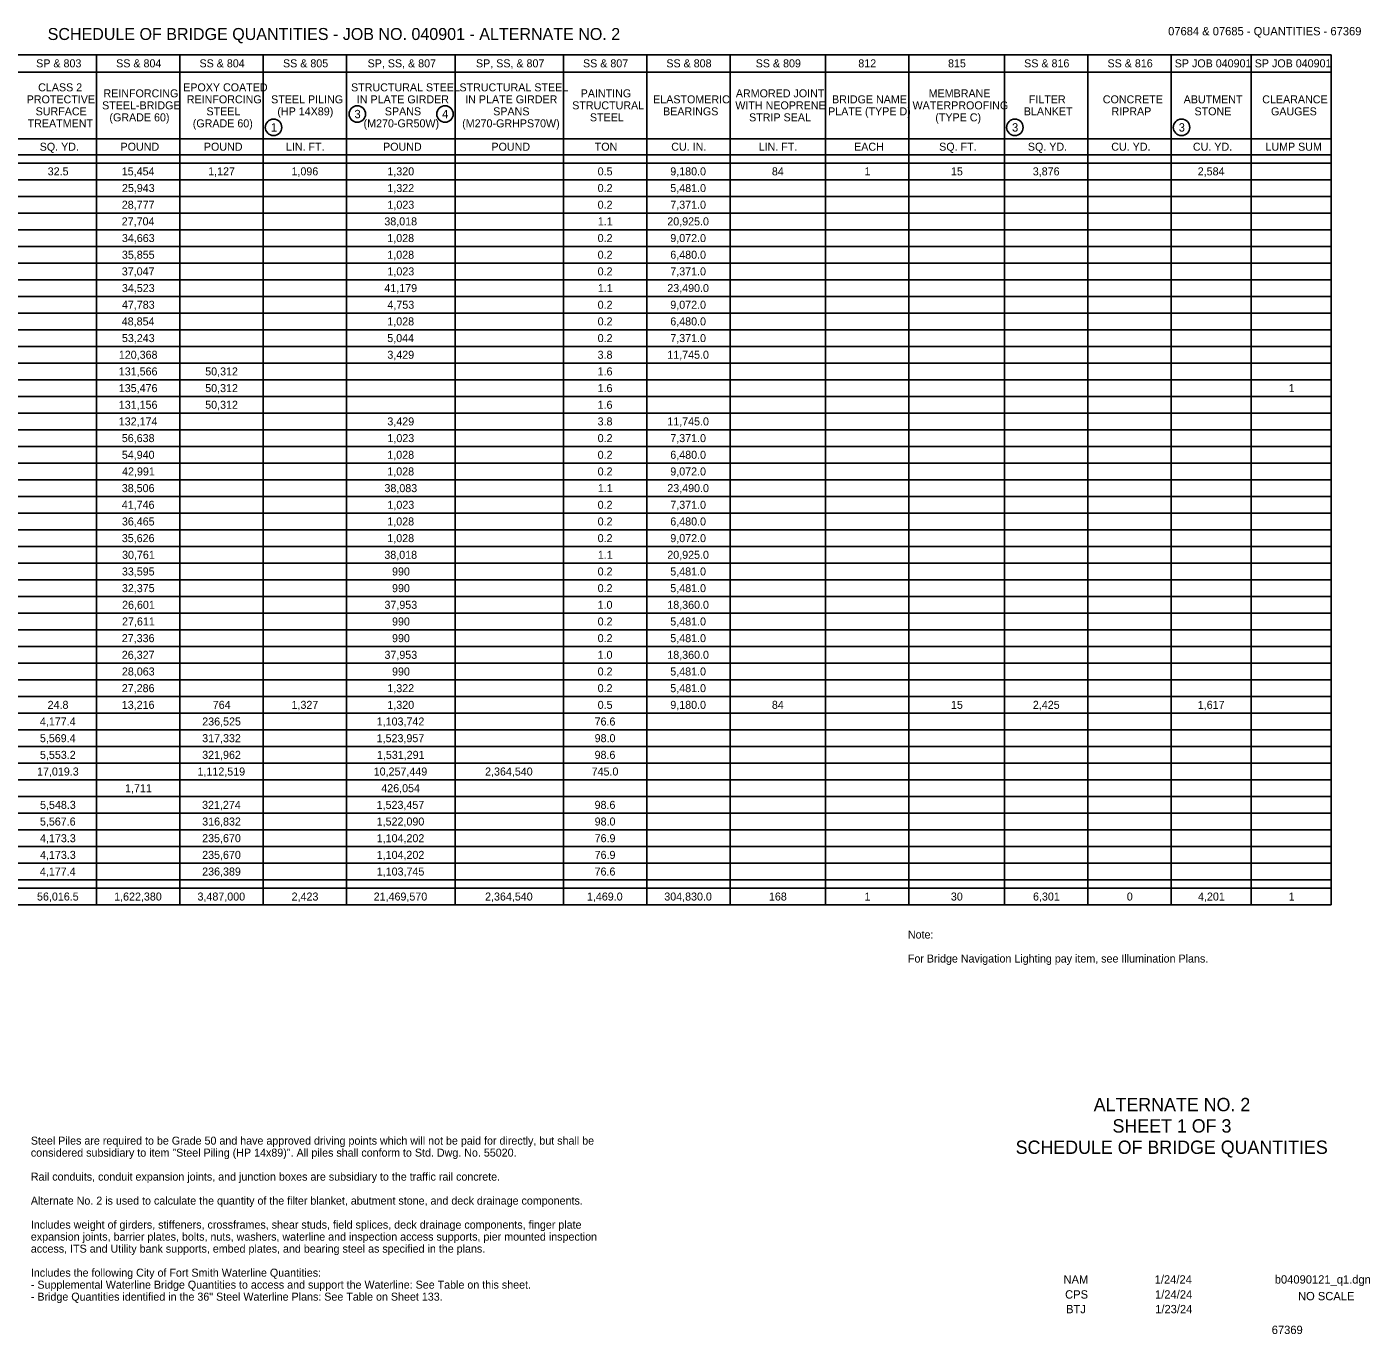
# Model space of a CAD drawing. Extents: x 0.06 to 1.36, y 0.04 to 0.85.
# Drawn here: x 0.519 to 1.358, y 0.037 to 0.854 of the extents above; entities that cross this region are included whole.
import ezdxf

# ---------------------------------------------------------------- set-up
doc = ezdxf.new("R2010")
doc.units = 0
for name, color, linetype in [('R_ROW', 7, 'Continuous'), ('R_Shade By Others', 7, 'Continuous'), ('R_Survey Control', 7, 'Continuous'), ('R_Wall', 7, 'Continuous')]:
    doc.layers.add(name, color=color, linetype=linetype)

msp = doc.modelspace()

# ---------------------------------------------------------------- linework, layer by layer
at = {"layer": 'R_Survey Control'}
for p, q in [((0.07508, 0.83695), (1.33392, 0.83695)), ((0.56236, 0.83695), (0.56236, 0.3057)), ((0.61444, 0.83695), (0.61444, 0.3057)), ((0.66653, 0.83695), (0.66653, 0.3057)), ((0.71861, 0.83695), (0.71861, 0.3057)), ((0.78632, 0.83695), (0.78632, 0.3057)), ((0.85407, 0.83695), (0.85407, 0.3057)), ((0.90615, 0.83695), (0.90615, 0.3057)), ((0.95823, 0.83695), (0.95823, 0.3057)), ((1.0178, 0.83695), (1.0178, 0.3057)), ((1.06988, 0.83695), (1.06988, 0.3057)), ((1.12978, 0.83695), (1.12978, 0.3057)), ((1.18186, 0.83695), (1.18186, 0.3057)), ((1.23394, 0.83695), (1.23394, 0.3057)), ((1.28392, 0.83695), (1.28392, 0.3057)), ((1.33392, 0.83695), (1.33392, 0.3057)), ((0.2593, 0.78445), (1.33392, 0.78445)), ((0.07508, 0.77445), (1.33392, 0.77445)), ((0.11154, 0.76924), (1.33392, 0.76924)), ((0.11154, 0.75883), (1.33392, 0.75883)), ((0.11154, 0.74841), (1.33392, 0.74841)), ((0.11154, 0.73799), (1.33392, 0.73799)), ((0.11154, 0.72758), (1.33392, 0.72758)), ((0.11154, 0.71716), (1.33392, 0.71716)), ((0.11154, 0.70674), (1.33392, 0.70674)), ((0.11154, 0.69633), (1.33392, 0.69633)), ((0.11154, 0.68591), (1.33392, 0.68591)), ((0.11154, 0.67549), (1.33392, 0.67549)), ((0.11154, 0.66508), (1.33392, 0.66508)), ((0.11154, 0.65466), (1.33392, 0.65466)), ((0.11154, 0.64424), (1.33392, 0.64424)), ((0.11154, 0.63383), (1.33392, 0.63383)), ((0.11154, 0.62341), (1.33392, 0.62341)), ((0.11154, 0.61299), (1.33392, 0.61299)), ((0.11154, 0.60258), (1.33392, 0.60258)), ((0.11154, 0.59216), (1.33392, 0.59216)), ((0.11154, 0.58174), (1.33392, 0.58174)), ((0.11154, 0.57133), (1.33392, 0.57133)), ((0.11154, 0.56091), (1.33392, 0.56091)), ((0.11154, 0.55049), (1.33392, 0.55049)), ((0.11154, 0.54008), (1.33392, 0.54008)), ((0.11154, 0.52966), (1.33392, 0.52966)), ((0.11154, 0.51924), (1.33392, 0.51924)), ((0.11154, 0.50883), (1.33392, 0.50883)), ((0.11154, 0.49841), (1.33392, 0.49841)), ((0.11154, 0.48799), (1.33392, 0.48799)), ((0.11154, 0.47758), (1.33392, 0.47758)), ((0.11154, 0.46716), (1.33392, 0.46716)), ((0.11154, 0.45674), (1.33392, 0.45674)), ((0.11154, 0.44633), (1.33392, 0.44633)), ((0.11154, 0.43591), (1.33392, 0.43591)), ((0.11154, 0.42549), (1.33392, 0.42549)), ((0.11154, 0.41508), (1.33392, 0.41508)), ((0.11154, 0.40466), (1.33392, 0.40466)), ((0.11154, 0.39424), (1.33392, 0.39424)), ((0.11154, 0.38383), (1.33392, 0.38383)), ((0.11154, 0.37341), (1.33392, 0.37341)), ((0.11154, 0.36299), (1.33392, 0.36299)), ((0.11154, 0.35258), (1.33392, 0.35258)), ((0.11154, 0.34216), (1.33392, 0.34216)), ((0.11154, 0.33174), (1.33392, 0.33174)), ((0.11154, 0.32133), (1.33392, 0.32133)), ((0.07508, 0.31612), (1.33392, 0.31612)), ((0.07508, 0.3057), (1.33392, 0.3057))]:
    msp.add_line(p, q, dxfattribs=at)
msp.add_lwpolyline([(0.2593, 0.82612), (0.30758, 0.82612), (0.41883, 0.82612), (0.46733, 0.82612), (0.509, 0.82612), (0.55587, 0.82612), (0.58452, 0.82612), (0.6366, 0.82612), (0.68087, 0.82612), (0.74858, 0.82612), (0.79433, 0.82612), (0.84642, 0.82612), (0.94537, 0.82612), (1.00267, 0.82612), (1.06517, 0.82612), (1.19277, 0.82612), (1.26048, 0.82612), (1.31256, 0.82612), (1.33392, 0.82612)], dxfattribs=at)
at = {"layer": 'R_Wall'}
for centre in [(0.72525, 0.79986), (0.78009, 0.79986), (0.67293, 0.79152), (1.13618, 0.79152), (1.24035, 0.79152)]:
    msp.add_circle(centre, 0.00515, dxfattribs=at)

# ---------------------------------------------------------------- texts
at = {"layer": 'R_ROW'}
msp.add_text('SCHEDULE OF BRIDGE QUANTITIES - JOB NO. 040901 - ALTERNATE NO. 2', height=0.0075, dxfattribs=at).set_placement((0.53175, 0.84612))
at = {"layer": 'R_Shade By Others'}
for s, height, p in [('07684 & 07685 - QUANTITIES - 67369', 0.0052083, (1.23197, 0.84904)), ('ALTERNATE NO. 2', 0.0083332, (1.18545, 0.17677)), ('SHEET 1 OF 3', 0.0083332, (1.1972, 0.16344)), ('SCHEDULE OF BRIDGE QUANTITIES', 0.0083332, (1.13669, 0.1501)), ('NAM', 0.005208, (1.1666, 0.06906)), ('1/24/24', 0.005208, (1.22357, 0.06906)), ('b04090121_q1.dgn', 0.0052083, (1.29862, 0.06906)), ('CPS', 0.005208, (1.1676, 0.05969)), ('1/24/24', 0.005208, (1.22378, 0.05969)), ('NO SCALE', 0.005208, (1.31316, 0.05864)), ('BTJ', 0.005208, (1.16819, 0.05052)), ('1/23/24', 0.005208, (1.22389, 0.05052)), ('67369', 0.005208, (1.29672, 0.03756))]:
    msp.add_text(s, height=height, dxfattribs=at).set_placement(p)
at = {"layer": 'R_Survey Control'}
for s, p in [('SP & 803', (0.52458, 0.82904)), ('SS & 804', (0.57457, 0.82904)), ('SS & 804', (0.62665, 0.82904)), ('SS & 805', (0.67883, 0.82904)), ('SP, SS, & 807', (0.7317, 0.82904)), ('SP, SS, & 807', (0.79943, 0.82904)), ('SS & 807', (0.86631, 0.82904)), ('SS & 808', (0.91839, 0.82904)), ('SS & 809', (0.97424, 0.82904)), ('812', (1.03836, 0.82904)), ('815', (1.09443, 0.82904)), ('SS & 816', (1.14201, 0.82904)), ('SS & 816', (1.19409, 0.82904)), ('SP JOB 040901', (1.2361, 0.82904)), ('SP JOB 040901', (1.2861, 0.82904)), ('CLASS 2', (0.52582, 0.81404)), ('REINFORCING', (0.56663, 0.81029)), ('EPOXY COATED', (0.61645, 0.81404)), ('STRUCTURAL STEEL', (0.72137, 0.81404)), ('STRUCTURAL STEEL', (0.78909, 0.81404)), ('PAINTING', (0.86485, 0.81029)), ('ARMORED JOINT', (0.96182, 0.81029)), ('MEMBRANE', (1.08232, 0.81029)), ('PROTECTIVE', (0.51866, 0.80654)), ('STEEL-BRIDGE', (0.56578, 0.80279)), ('REINFORCING', (0.61871, 0.80654)), ('STEEL PILING', (0.67141, 0.80654)), ('IN PLATE GIRDER', (0.72497, 0.80654)), ('IN PLATE GIRDER', (0.7927, 0.80654)), ('STRUCTURAL', (0.85957, 0.80279)), ('ELASTOMERIC', (0.91013, 0.80654)), ('WITH NEOPRENE', (0.9615, 0.80279)), ('BRIDGE NAME', (1.02194, 0.80654)), ('WATERPROOFING', (1.07225, 0.80279)), ('FILTER', (1.14491, 0.80654)), ('CONCRETE', (1.19116, 0.80654)), ('ABUTMENT', (1.24169, 0.80654)), ('CLEARANCE', (1.29079, 0.80654)), ('SURFACE', (0.52424, 0.79904)), ('(GRADE 60)', (0.57037, 0.79529)), ('STEEL', (0.631, 0.79904)), ('(HP 14X89)', (0.67532, 0.79904)), ('SPANS', (0.74247, 0.79904)), ('SPANS', (0.81019, 0.79904)), ('STEEL', (0.87063, 0.79529)), ('BEARINGS', (0.91634, 0.79904)), ('STRIP SEAL', (0.9701, 0.79529)), ('PLATE (TYPE D)', (1.01949, 0.79904)), ('(TYPE C)', (1.08648, 0.79529)), ('BLANKET', (1.14177, 0.79904)), ('RIPRAP', (1.19656, 0.79904)), ('STONE', (1.24846, 0.79904)), ('GAUGES', (1.29626, 0.79904)), ('TREATMENT', (0.51926, 0.79154)), ('(GRADE 60)', (0.62245, 0.79154)), ('(M270-GR50W)', (0.7292, 0.79154)), ('(M270-GRHPS70W)', (0.7908, 0.79154)), ('SQ. YD.', (0.52679, 0.77695)), ('POUND', (0.5773, 0.77695)), ('POUND', (0.62938, 0.77695)), ('LIN. FT.', (0.68065, 0.77695)), ('POUND', (0.74136, 0.77695)), ('POUND', (0.80909, 0.77695)), ('TON', (0.87363, 0.77695)), ('CU. IN.', (0.92146, 0.77695)), ('LIN. FT.', (0.97609, 0.77695)), ('EACH', (1.03572, 0.77695)), ('SQ. FT.', (1.0889, 0.77695)), ('SQ. YD.', (1.14432, 0.77695)), ('CU. YD.', (1.19643, 0.77695)), ('CU. YD.', (1.24746, 0.77695)), ('LUMP SUM', (1.29277, 0.77695)), ('32.5', (0.53179, 0.76154)), ('15,454', (0.57806, 0.76154)), ('1,127', (0.63206, 0.76154)), ('1,096', (0.68414, 0.76154)), ('1,320', (0.74406, 0.76154)), ('0.5', (0.87549, 0.76154)), ('9,180.0', (0.92087, 0.76154)), ('84', (0.98435, 0.76154)), ('1', (1.04224, 0.76154)), ('15', (1.09625, 0.76154)), ('3,876', (1.14739, 0.76154)), ('2,584', (1.25047, 0.76154)), ('25,943', (0.57817, 0.75112)), ('1,322', (0.74407, 0.75112)), ('0.2', (0.87547, 0.75112)), ('5,481.0', (0.92087, 0.75112)), ('28,777', (0.5781, 0.7407)), ('1,023', (0.74411, 0.7407)), ('0.2', (0.87547, 0.7407)), ('7,371.0', (0.92087, 0.7407)), ('27,704', (0.57806, 0.73029)), ('38,018', (0.74217, 0.73029)), ('1.1', (0.87559, 0.73029)), ('20,925.0', (0.91899, 0.73029)), ('34,663', (0.57817, 0.71987)), ('1,028', (0.74404, 0.71987)), ('0.2', (0.87547, 0.71987)), ('9,072.0', (0.92087, 0.71987)), ('35,855', (0.57816, 0.70945)), ('1,028', (0.74404, 0.70945)), ('0.2', (0.87547, 0.70945)), ('6,480.0', (0.92087, 0.70945)), ('37,047', (0.5781, 0.69904)), ('1,023', (0.74411, 0.69904)), ('0.2', (0.87547, 0.69904)), ('7,371.0', (0.92087, 0.69904)), ('34,523', (0.57817, 0.68862)), ('41,179', (0.74218, 0.68862)), ('1.1', (0.87559, 0.68862)), ('23,490.0', (0.91899, 0.68862)), ('47,783', (0.57817, 0.6782)), ('4,753', (0.74411, 0.6782)), ('0.2', (0.87547, 0.6782)), ('9,072.0', (0.92087, 0.6782)), ('48,854', (0.57806, 0.66779)), ('1,028', (0.74404, 0.66779)), ('0.2', (0.87547, 0.66779)), ('6,480.0', (0.92087, 0.66779)), ('53,243', (0.57817, 0.65737)), ('5,044', (0.744, 0.65737)), ('0.2', (0.87547, 0.65737)), ('7,371.0', (0.92087, 0.65737)), ('120,368', (0.57623, 0.64695)), ('3,429', (0.74406, 0.64695)), ('3.8', (0.87544, 0.64695)), ('11,745.0', (0.91899, 0.64695)), ('131,566', (0.57622, 0.63654)), ('50,312', (0.63021, 0.63654)), ('1.6', (0.87543, 0.63654)), ('135,476', (0.57622, 0.62612)), ('50,312', (0.63021, 0.62612)), ('1.6', (0.87543, 0.62612)), ('1', (1.30732, 0.62612)), ('131,156', (0.57622, 0.6157)), ('50,312', (0.63021, 0.6157)), ('1.6', (0.87543, 0.6157)), ('132,174', (0.57619, 0.60529)), ('3,429', (0.74406, 0.60529)), ('3.8', (0.87544, 0.60529)), ('11,745.0', (0.91899, 0.60529)), ('56,638', (0.5781, 0.59487)), ('1,023', (0.74411, 0.59487)), ('0.2', (0.87547, 0.59487)), ('7,371.0', (0.92087, 0.59487)), ('54,940', (0.57812, 0.58445)), ('1,028', (0.74404, 0.58445)), ('0.2', (0.87547, 0.58445)), ('6,480.0', (0.92087, 0.58445)), ('42,991', (0.57826, 0.57404)), ('1,028', (0.74404, 0.57404)), ('0.2', (0.87547, 0.57404)), ('9,072.0', (0.92087, 0.57404)), ('38,506', (0.57809, 0.56362)), ('38,083', (0.74224, 0.56362)), ('1.1', (0.87559, 0.56362)), ('23,490.0', (0.91899, 0.56362)), ('41,746', (0.57809, 0.5532)), ('1,023', (0.74411, 0.5532)), ('0.2', (0.87547, 0.5532)), ('7,371.0', (0.92087, 0.5532)), ('36,465', (0.57816, 0.54279)), ('1,028', (0.74404, 0.54279)), ('0.2', (0.87547, 0.54279)), ('6,480.0', (0.92087, 0.54279)), ('35,626', (0.57809, 0.53237)), ('1,028', (0.74404, 0.53237)), ('0.2', (0.87547, 0.53237)), ('9,072.0', (0.92087, 0.53237)), ('30,761', (0.57826, 0.52195)), ('38,018', (0.74217, 0.52195)), ('1.1', (0.87559, 0.52195)), ('20,925.0', (0.91899, 0.52195)), ('33,595', (0.57816, 0.51154)), ('990', (0.74697, 0.51154)), ('0.2', (0.87547, 0.51154)), ('5,481.0', (0.92087, 0.51154)), ('32,375', (0.57816, 0.50112)), ('990', (0.74697, 0.50112)), ('0.2', (0.87547, 0.50112)), ('5,481.0', (0.92087, 0.50112)), ('26,601', (0.57826, 0.4907)), ('37,953', (0.74224, 0.4907)), ('1.0', (0.87545, 0.4907)), ('18,360.0', (0.91899, 0.4907)), ('27,611', (0.57826, 0.48029)), ('990', (0.74697, 0.48029)), ('0.2', (0.87547, 0.48029)), ('5,481.0', (0.92087, 0.48029)), ('27,336', (0.57809, 0.46987)), ('990', (0.74697, 0.46987)), ('0.2', (0.87547, 0.46987)), ('5,481.0', (0.92087, 0.46987)), ('26,327', (0.5781, 0.45945)), ('37,953', (0.74224, 0.45945)), ('1.0', (0.87545, 0.45945)), ('18,360.0', (0.91899, 0.45945)), ('28,063', (0.57817, 0.44904)), ('990', (0.74697, 0.44904)), ('0.2', (0.87547, 0.44904)), ('5,481.0', (0.92087, 0.44904)), ('27,286', (0.57809, 0.43862)), ('1,322', (0.74407, 0.43862)), ('0.2', (0.87547, 0.43862)), ('5,481.0', (0.92087, 0.43862)), ('24.8', (0.53174, 0.4282)), ('13,216', (0.57809, 0.4282)), ('764', (0.63494, 0.4282)), ('1,327', (0.68415, 0.4282)), ('1,320', (0.74406, 0.4282)), ('0.5', (0.87549, 0.4282)), ('9,180.0', (0.92087, 0.4282)), ('84', (0.98435, 0.4282)), ('15', (1.09625, 0.4282)), ('2,425', (1.14745, 0.4282)), ('1,617', (1.25051, 0.4282)), ('4,177.4', (0.52691, 0.41779)), ('236,525', (0.62837, 0.41779)), ('1,103,742', (0.7374, 0.41779)), ('76.6', (0.87355, 0.41779)), ('5,569.4', (0.52691, 0.40737)), ('317,332', (0.62834, 0.40737)), ('1,523,957', (0.73737, 0.40737)), ('98.0', (0.87358, 0.40737)), ('5,553.2', (0.52697, 0.39695)), ('321,962', (0.62834, 0.39695)), ('1,531,291', (0.73753, 0.39695)), ('98.6', (0.87355, 0.39695)), ('17,019.3', (0.52514, 0.38654)), ('1,112,519', (0.62541, 0.38654)), ('10,257,449', (0.73551, 0.38654)), ('2,364,540', (0.80512, 0.38654)), ('745.0', (0.8717, 0.38654)), ('1,711', (0.58013, 0.37612)), ('426,054', (0.74025, 0.37612)), ('5,548.3', (0.52702, 0.3657)), ('321,274', (0.62827, 0.3657)), ('1,523,457', (0.73737, 0.3657)), ('98.6', (0.87355, 0.3657)), ('5,567.6', (0.52693, 0.35529)), ('316,832', (0.62834, 0.35529)), ('1,522,090', (0.73739, 0.35529)), ('98.0', (0.87358, 0.35529)), ('4,173.3', (0.52702, 0.34487)), ('235,670', (0.62832, 0.34487)), ('1,104,202', (0.7374, 0.34487)), ('76.9', (0.87358, 0.34487)), ('4,173.3', (0.52702, 0.33445)), ('235,670', (0.62832, 0.33445)), ('1,104,202', (0.7374, 0.33445)), ('76.9', (0.87358, 0.33445)), ('4,177.4', (0.52691, 0.32404)), ('236,389', (0.62833, 0.32404)), ('1,103,745', (0.73743, 0.32404)), ('76.6', (0.87355, 0.32404)), ('56,016.5', (0.52512, 0.30841)), ('1,622,380', (0.57332, 0.30841)), ('3,487,000', (0.62541, 0.30841)), ('2,423', (0.68422, 0.30841)), ('21,469,570', (0.73551, 0.30841)), ('2,364,540', (0.80512, 0.30841)), ('1,469.0', (0.86878, 0.30841)), ('304,830.0', (0.91711, 0.30841)), ('168', (0.98251, 0.30841)), ('1', (1.04224, 0.30841)), ('30', (1.09621, 0.30841)), ('6,301', (1.14755, 0.30841)), ('0', (1.20616, 0.30841)), ('4,201', (1.25066, 0.30841)), ('1', (1.30732, 0.30841)), ('Note:', (1.06935, 0.28467)), ('For Bridge Navigation Lighting pay item, see Illumination Plans.', (1.06935, 0.26967))]:
    msp.add_text(s, height=0.005, dxfattribs=at).set_placement(p)
at = {"layer": 'R_Wall'}
for s, height, p in [('3', 0.00521, (0.7235, 0.79725)), ('4', 0.00521, (0.77822, 0.79725)), ('1', 0.00521, (0.67127, 0.78892)), ('3', 0.00521, (1.13443, 0.78892)), ('3', 0.00521, (1.2386, 0.78892)), ('Steel Piles are required to be Grade 50 and have approved driving points which will not be paid for directly, but shall be ', 0.005, (0.52126, 0.1559)), ('considered subsidiary to item "Steel Piling (HP 14x89)". All piles shall conform to Std. Dwg. No. 55020.', 0.005, (0.52126, 0.1484)), ('Rail conduits, conduit expansion joints, and junction boxes are subsidiary to the traffic rail concrete.', 0.005, (0.52126, 0.1334)), ('Alternate No. 2 is used to calculate the quantity of the filter blanket, abutment stone, and deck drainage components.', 0.005, (0.52126, 0.1184)), ('expansion joints, barrier plates, bolts, nuts, washers, waterline and inspection access supports, pier mounted inspection ', 0.005, (0.52126, 0.0959)), ('Includes weight of girders, stiffeners, crossframes, shear studs, field splices, deck drainage components, finger plate ', 0.005, (0.52126, 0.1034)), ('access, ITS and Utility bank supports, embed plates, and bearing steel as specified in the plans.', 0.005, (0.52126, 0.0884)), ('Includes the following City of Fort Smith Waterline Quantities:', 0.005, (0.52126, 0.0734)), ('- Supplemental Waterline Bridge Quantities to access and support the Waterline: See Table on this sheet.', 0.005, (0.52126, 0.0659)), ('- Bridge Quantities identified in the 36" Steel Waterline Plans: See Table on Sheet 133.', 0.005, (0.52126, 0.0584))]:
    msp.add_text(s, height=height, dxfattribs=at).set_placement(p)

doc.saveas('drawing.dxf')
